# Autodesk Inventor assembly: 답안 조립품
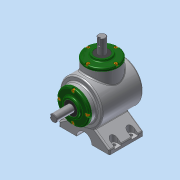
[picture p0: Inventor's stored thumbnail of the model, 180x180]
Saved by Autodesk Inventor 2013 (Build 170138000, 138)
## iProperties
Created: 2017-04
Part Number: 답안 조립품
Document SubType Name: Assembly
Designer: Administrator
Author: Administrator
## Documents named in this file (14)
- C:\Users\Administrator\Desktop\470407V1012\답안 조립품.iam
- C:\Users\Administrator\Desktop\470407V1012\본체.ipt
- C:\Users\Administrator\Desktop\470407V1012\메인 베벨기어.ipt
- C:\Users\Administrator\Desktop\470407V1012\메인 축.ipt
- 메인 축.ipt
- C:\Users\Administrator\Desktop\470407V1012\서브 축.ipt
- 서브 축.ipt
- C:\Users\Administrator\Desktop\470407V1012\서브 베벨기어.ipt
- C:\Users\Administrator\Desktop\470407V1012\키 5x5.ipt
- C:\Users\Administrator\Desktop\470407V1012\키 4x4.ipt
- C:\Users\Administrator\Desktop\470407V1012\베어링 6203.ipt
- C:\Users\Administrator\Desktop\470407V1012\커버.ipt
- C:\Users\Administrator\Desktop\470407V1012\오일실 17 32 8.ipt
- C:\Users\Administrator\Desktop\470407V1012\볼트 M4.ipt
